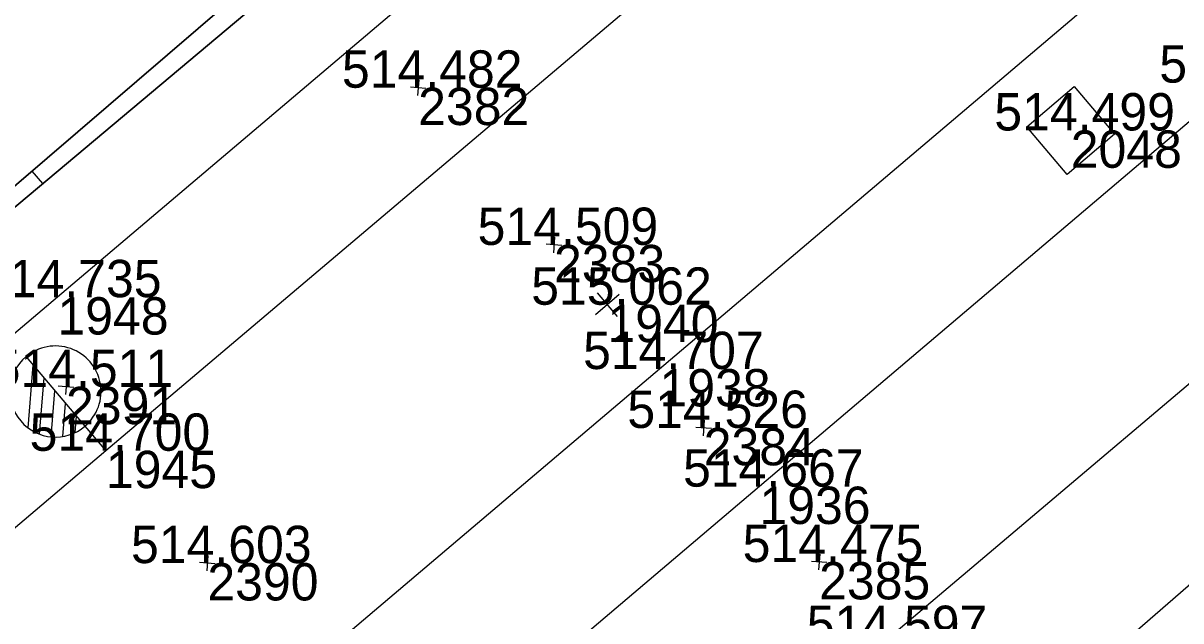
# Model space of a CAD drawing. Extents: x -1234191 to 23050, y -1290331 to -741191.
# Drawn here: x -865276.85 to -865239.66, y -1104857.81 to -1104838.6 of the extents above; entities that cross this region are included whole.
import ezdxf

# ---------------------------------------------------------------- set-up
doc = ezdxf.new("R2010")
doc.units = 0
for name, color, linetype in [('Vrstva 1', 7, 'Continuous'), ('Vrstva 16', 7, 'Continuous'), ('Vrstva 2', 7, 'Continuous'), ('Vrstva 4', 7, 'Continuous'), ('Vrstva 41', 7, 'Continuous'), ('Vrstva 48', 7, 'Continuous'), ('Vrstva 49', 7, 'Continuous'), ('Vrstva 60', 7, 'Continuous'), ('Vrstva 61', 7, 'Continuous'), ('Vrstva 7', 7, 'Continuous')]:
    doc.layers.add(name, color=color, linetype=linetype)

msp = doc.modelspace()

# ---------------------------------------------------------------- linework, layer by layer
at = {"layer": 'Vrstva 1'}
for points in [[(-865172.427, -1104762.412), (-865185.591, -1104772.43), (-865197.097, -1104781.213), (-865206.094, -1104788.365), (-865212.838, -1104794.025), (-865223.77, -1104803.315), (-865250.415, -1104825.925), (-865275.746, -1104847.411), (-865305.187, -1104872.372)], [(-865172.427, -1104762.412), (-865184.425, -1104773.857), (-865195.058, -1104784.009), (-865203.639, -1104792.098), (-865210.038, -1104797.846), (-865220.596, -1104806.903), (-865247.252, -1104829.534), (-865274.188, -1104852.347), (-865282.212, -1104859.155)], [(-865167.713, -1104779.363), (-865179.796, -1104790.726), (-865184.478, -1104795.035), (-865190.97, -1104800.752), (-865195.945, -1104804.963), (-865211.087, -1104817.791), (-865237.902, -1104840.516), (-865253.199, -1104853.499), (-865272.037, -1104869.497), (-865292.913, -1104887.204), (-865297.954, -1104891.507), (-865305.977, -1104898.32), (-865318.53, -1104909.524), (-865330.274, -1104921.076), (-865350.227, -1104943.561), (-865366.81, -1104965.604), (-865377.819, -1104982.561), (-865389.023, -1105002.397), (-865401.608, -1105028.878), (-865411.418, -1105054.9), (-865419.263, -1105081.952), (-865424.901, -1105109.6), (-865427.484, -1105128.881), (-865429.29, -1105156.421)], [(-865191.596, -1104807.426), (-865203.701, -1104818.823), (-865217.829, -1104831.696), (-865233.858, -1104845.514), (-865249.226, -1104858.523), (-865268.126, -1104874.441), (-865288.794, -1104891.939), (-865293.631, -1104896.045), (-865301.695, -1104902.998), (-865314.06, -1104914.085), (-865325.819, -1104925.585), (-865345.471, -1104947.527), (-865361.673, -1104969.039), (-865372.543, -1104985.71), (-865383.576, -1105005.459), (-865395.524, -1105031.668), (-865404.617, -1105057.472), (-865411.5, -1105084.11), (-865416.451, -1105111.219), (-865418.889, -1105130.073), (-865420.897, -1105156.736)], [(-865191.596, -1104807.426), (-865202.38, -1104820.104), (-865215.324, -1104834.358), (-865230.542, -1104848.969), (-865245.791, -1104862.223), (-865264.946, -1104878.392), (-865285.377, -1104895.631), (-865290.186, -1104899.737), (-865298.334, -1104906.713), (-865310.624, -1104917.685), (-865322.166, -1104929.038), (-865341.482, -1104950.693), (-865357.568, -1104971.918), (-865368.111, -1104988.11), (-865379.223, -1105007.986), (-865390.73, -1105033.129), (-865399.103, -1105056.556), (-865405.793, -1105081.424), (-865410.584, -1105106.207), (-865413.892, -1105131.231), (-865415.794, -1105156.578)], [(-865214.42, -1104814.068), (-865241.183, -1104836.797), (-865256.409, -1104849.72), (-865275.283, -1104865.734), (-865296.129, -1104883.416), (-865301.469, -1104887.956), (-865309.155, -1104894.547), (-865321.846, -1104905.934), (-865333.869, -1104917.682), (-865354.051, -1104940.12), (-865371.183, -1104962.558), (-865382.53, -1104979.664), (-865394.153, -1104999.759), (-865407.109, -1105026.401), (-865417.481, -1105052.831), (-865425.89, -1105080.546), (-865431.949, -1105108.222), (-865434.948, -1105128.258), (-865437.242, -1105156.147)]]:
    msp.add_lwpolyline(points, dxfattribs=at)
at = {"layer": 'Vrstva 16'}
msp.add_lwpolyline([(-865236.417, -1104809.338), (-865250.281, -1104821.229), (-865250.806, -1104821.687), (-865252.83, -1104823.595), (-865254.11, -1104822.138), (-865255.982, -1104823.627), (-865254.785, -1104825.159), (-865260.122, -1104829.875), (-865260.68, -1104829.8), (-865265.39, -1104833.748), (-865281.926, -1104847.956), (-865285.122, -1104844.586), (-865281.374, -1104841.282), (-865283.623, -1104838.764), (-865278.644, -1104832.457), (-865274.436, -1104828.636), (-865276.278, -1104826.618), (-865274.29, -1104824.802), (-865276.342, -1104822.554)], dxfattribs=at)
at = {"layer": 'Vrstva 2'}
for p, q in [((-865276.756, -1104849.325), (-865276.755, -1104849.324)), ((-865276.755, -1104849.324), (-865274.862, -1104851.557)), ((-865276.69, -1104851.606), (-865276.524, -1104849.596)), ((-865276.325, -1104851.807), (-865276.177, -1104850.006)), ((-865275.951, -1104851.894), (-865275.829, -1104850.416)), ((-865275.569, -1104851.882), (-865275.482, -1104850.826)), ((-865275.177, -1104851.758), (-865275.134, -1104851.236)), ((-865274.863, -1104851.556), (-865274.188, -1104852.347))]:
    msp.add_line(p, q, dxfattribs=at)
msp.add_lwpolyline([(-865274.188, -1104852.347), (-865282.212, -1104859.155)], dxfattribs=at)
for centre, radius, start, end in [((-865275.807, -1104850.441), 1.462, 310.2436, 130.7131), ((-865275.809, -1104850.441), 1.464, 130.3331, 310.2939)]:
    msp.add_arc(centre, radius, start, end, dxfattribs=at)
at = {"layer": 'Vrstva 4'}
msp.add_lwpolyline([(-865399.899, -1104984.692), (-865395.339, -1104973.904), (-865391.092, -1104966.952), (-865390.358, -1104965.753), (-865393.456, -1104963.82), (-865384.119, -1104950.272), (-865373.223, -1104935.927), (-865360.521, -1104921.051), (-865348.571, -1104908.459), (-865342.951, -1104901.703), (-865328.055, -1104887.691), (-865317.916, -1104877.902), (-865307.354, -1104869.474), (-865290.274, -1104855.615), (-865281.53, -1104848.213), (-865264.87, -1104834.221), (-865260.122, -1104829.875), (-865250.382, -1104822.206), (-865249.872, -1104821.732), (-865216.282, -1104793.053), (-865215.784, -1104792.594), (-865182.298, -1104766.391), (-865181.776, -1104765.981), (-865167.226, -1104750.941)], dxfattribs=at)
at = {"layer": 'Vrstva 41'}
msp.add_lwpolyline([(-865241.789, -1104842.168), (-865243.314, -1104843.463), (-865244.609, -1104841.938), (-865243.084, -1104840.643), (-865241.789, -1104842.168)], dxfattribs=at)
at = {"layer": 'Vrstva 48'}
msp.add_line((-865276.573, -1104843.356), (-865276.227, -1104843.759), dxfattribs=at)
at = {"layer": 'Vrstva 49'}
for p, q in [((-865263.911, -1104840.699), (-865264.409, -1104840.659)), ((-865264.14, -1104840.43), (-865264.18, -1104840.928)), ((-865259.775, -1104845.482), (-865259.817, -1104845.98)), ((-865259.547, -1104845.752), (-865260.045, -1104845.71)), ((-865275.221, -1104850.314), (-865275.719, -1104850.272)), ((-865275.449, -1104850.044), (-865275.491, -1104850.542)), ((-865254.968, -1104851.364), (-865255.008, -1104851.862)), ((-865254.739, -1104851.633), (-865255.237, -1104851.593)), ((-865270.91, -1104855.707), (-865270.95, -1104856.205)), ((-865251.032, -1104855.941), (-865251.53, -1104855.901)), ((-865251.261, -1104855.672), (-865251.301, -1104856.17)), ((-865270.681, -1104855.976), (-865271.179, -1104855.936))]:
    msp.add_line(p, q, dxfattribs=at)
for points in [[(-865348.571, -1104908.459), (-865349.724, -1104907.399), (-865344.105, -1104900.866), (-865329.173, -1104886.274), (-865317.881, -1104876.032), (-865308.241, -1104868.667), (-865290.739, -1104854.995), (-865287.123, -1104852.127), (-865281.926, -1104847.956), (-865265.39, -1104833.748), (-865260.68, -1104829.8), (-865260.122, -1104829.875)], [(-865260.122, -1104829.875), (-865264.87, -1104834.221), (-865281.53, -1104848.213), (-865290.274, -1104855.615), (-865307.354, -1104869.474), (-865317.916, -1104877.902), (-865328.055, -1104887.691), (-865342.951, -1104901.703), (-865348.571, -1104908.459)]]:
    msp.add_lwpolyline(points, dxfattribs=at)
at = {"layer": 'Vrstva 60'}
for p, q in [((-865264.16, -1104840.679), (-865264.16, -1104840.679)), ((-865243.199, -1104842.053), (-865243.199, -1104842.053)), ((-865259.796, -1104845.731), (-865259.796, -1104845.731)), ((-865275.746, -1104847.411), (-865275.746, -1104847.411)), ((-865258.08, -1104847.653), (-865258.08, -1104847.653)), ((-865256.409, -1104849.72), (-865256.409, -1104849.72)), ((-865275.47, -1104850.293), (-865275.47, -1104850.293)), ((-865254.988, -1104851.613), (-865254.988, -1104851.613)), ((-865274.188, -1104852.347), (-865274.188, -1104852.347)), ((-865253.199, -1104853.499), (-865253.199, -1104853.499)), ((-865270.93, -1104855.956), (-865270.93, -1104855.956)), ((-865251.281, -1104855.921), (-865251.281, -1104855.921))]:
    msp.add_line(p, q, dxfattribs=at)
at = {"layer": 'Vrstva 7'}
for p, q in [((-865257.699, -1104847.329), (-865258.461, -1104847.977)), ((-865257.756, -1104848.034), (-865258.404, -1104847.272))]:
    msp.add_line(p, q, dxfattribs=at)

# ---------------------------------------------------------------- texts
at = {"layer": 'Vrstva 60'}
for s, p in [('2382', (-865264.16, -1104841.879)), ('2048', (-865243.199, -1104843.253)), ('2383', (-865259.796, -1104846.931)), ('1948', (-865275.746, -1104848.611)), ('1940', (-865258.08, -1104848.853)), ('1938', (-865256.409, -1104850.92)), ('2391', (-865275.47, -1104851.493)), ('2384', (-865254.988, -1104852.813)), ('1945', (-865274.188, -1104853.547)), ('1936', (-865253.199, -1104854.699)), ('2385', (-865251.281, -1104857.121)), ('2390', (-865270.93, -1104857.156))]:
    msp.add_text(s, height=1.2, dxfattribs=at).set_placement(p)
at = {"layer": 'Vrstva 61'}
for s, p in [('514.482', (-865266.608, -1104840.679)), ('514.597', (-865240.354, -1104840.516)), ('514.499', (-865245.653, -1104842.053)), ('514.509', (-865262.25, -1104845.731)), ('514.735', (-865278.202, -1104847.411)), ('515.062', (-865260.528, -1104847.653)), ('514.707', (-865258.861, -1104849.72)), ('514.511', (-865277.827, -1104850.293)), ('514.526', (-865257.44, -1104851.613)), ('514.700', (-865276.639, -1104852.347)), ('514.667', (-865255.651, -1104853.499)), ('514.603', (-865273.382, -1104855.956)), ('514.475', (-865253.737, -1104855.921)), ('514.597', (-865251.678, -1104858.523))]:
    msp.add_text(s, height=1.2, dxfattribs=at).set_placement(p)

doc.saveas('drawing.dxf')
